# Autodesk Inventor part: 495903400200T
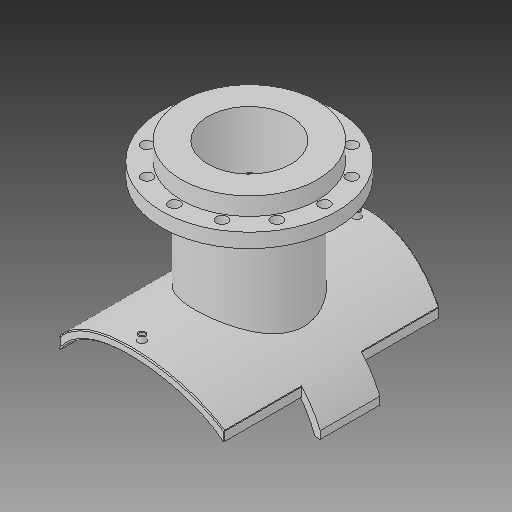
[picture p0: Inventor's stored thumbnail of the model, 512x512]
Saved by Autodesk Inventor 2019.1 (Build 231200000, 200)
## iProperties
Created: 2017-10
Part Number: 495903400200T
Material: Generic
Description: PLASSON FLANGED BRANCH SADDLE 400X200
Document SubType Name: Modeling
Designer: KIM
Mass: 2339.99 g
Surface Area: 3251.55 cm^2
Volume: 2339.99 cm^3
Density: 1 g/cm^3
Appearance: Default
Author: KIM
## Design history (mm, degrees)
derived "495904_495903.ipt"
feature "Solid1::495904_495903.ipt"
feature "Solid2::495904_495903.ipt"
tag "TaggingFeature1"
body "Solid1"
other parameters: "d1" = 15, "d2" = 324, "d4" = 0, "d6" = 117.5, "d7" = 0, "d12" = 225.6, "d13" = 14, "d14" = 211.5, "d16" = 5 deg, "d18" = 4, "d19" = 14, "d20" = 0, "d21" = 3, "d22" = 0, "d23" = 465, "d36" = 211.5, "d38" = 0, "d39" = 2, "d41" = 163, "d42" = 268, "d43" = 344, "d46" = 214.4, "d47" = 16, "d48" = 10.4, "d49" = 175, "d51" = 408, "d53" = 0, "d54" = 22, "d55" = 147.5, "d57" = 0, "d59" = 360 deg, "d61" = 28, "d63" = 0, "d67" = 15, "d68" = 125, "d70" = 0, "d71" = 2, "d_1" = 268, "x_" = 15, "D_" = 16, "DN_" = 163, "D_1" = 344, "t_" = 28, "s_" = 22, "Dp_" = 295
